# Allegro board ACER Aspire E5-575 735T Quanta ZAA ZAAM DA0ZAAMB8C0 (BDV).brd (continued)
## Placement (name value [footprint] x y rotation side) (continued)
Q22  ioac@ao3413  [SOT23_213-3_3-2]  205.67 190.77 90 bottom
Q23  2n7002dw  [SC70-2_1-65-6P]  178.87 179.22 270 bottom
Q24  ioac@ao3413  [SOT23_213-3_3-2]  48.06 67.58 0 top
Q25  2n7002k  [SOT23_213-3_3-2]  31.17 62.88 270 top
Q26  ap2331sa-7  [SOT23_213-3_3-2]  18.6 58.06 180 top
Q27  *dtc144eu  [UMT_213-3-1_3]  195 50.18 270 bottom
Q28  *ao3404  [SOT23_213-3_3-2]  199.83 51.96 180 bottom
Q29  *pja138k  [SOT23_213-3_3-2]  191.57 50.31 90 bottom
Q30  2n7002k  [SOT23_213-3_3-2]  192.59 31.39 90 bottom
Q31  fdv301n  [SOT23_213-3_3-2]  88.32 130.45 270 bottom
Q32  2n7002dw  [SC70-2_1-65-6P]  148.01 125.62 180 bottom
Q34  ioac@ao6402a  [TSOP6-2_8-95]  222.43 100.48 180 bottom
Q35  *dtc144eu  [UMT_213-3-1_3]  92.89 102.89 0 bottom
Q36  ioac@dmn601k-7  [SOT23_213-3_3-2]  225.35 105.94 0 bottom
Q37  ioac@2n7002dw  [SC70-2_1-65-6P]  225.35 108.86 0 bottom
Q38  *ioac@ao3413  [SOT23_213-3_3-2]  205.29 186.96 270 bottom
Q39  ioac@2n7002k  [SOT23_213-3_3-2]  45.4 80.41 180 top
Q40  pja138k  [SOT23_213-3_3-2]  218.12 67.58 0 bottom
Q41  *2n7002k  [SOT23_213-3_3-2]  25.71 56.79 270 top
Q42  *ao3413  [SOT23_213-3_3-2]  132.52 12.97 90 bottom
Q43  *tdi@2n7002dw  [SC70-2_1-65-6P]  137.72 15.01 180 bottom
Q56  *pj4n3kdw  [SC70-2_1-65-6P]  218.75 71.77 90 bottom
Q59  2n7002k  [SOT23_213-3_3-2]  169.98 109.87 180 bottom
Q75  fpd@ao3413  [SOT23_213-3_3-2]  113.09 32.4 90 top
Q4000  ev@ao3413  [SOT23_213-3_3-2]  170.11 111.02 270 top
Q4001  ev@2n7002k  [SOT23_213-3_3-2]  166.17 111.02 270 top
Q4002  ev@2n7002kw_115ma  [UMT_213-3-1_3]  164.65 116.48 0 top
Q4200  ev@dtc144eu  [UMT_213-3-1_3]  177.89 107.29 270 bottom
Q4201  ev@mmbt3904-7-f  [SOT23_213-3_3-2]  173.55 107.17 270 bottom
Q4202  ev@dtc144eua  [UMT_213-3-1_3]  163.89 135.53 90 bottom
Q4203  ev@metr3904-g  [SOT23_213-3_3-2]  163.63 139.34 90 bottom
Q4300  *ev@me2n7002dkw-g_115ma  [SC70-2_1-65-6P]  191.32 105.94 180 bottom
Q4301  ev@me2n7002dkw-g_115ma  [SC70-2_1-65-6P]  171.38 116.22 0 top
Q4302  ev@me2n7002dkw-g_115ma  [SC70-2_1-65-6P]  185.6 108.86 180 bottom
Q4500  gkb@2n7002d  [SOT23_213-3_3-2]  206.69 159.15 270 bottom
Q4501  gkb@2n7002d  [SOT23_213-3_3-2]  178.11 174.14 0 bottom
Q4509  gka@2n7002d  [SOT23_213-3_3-2]  226.99 117.47 90 top
Q4510  gka@2n7002d  [SOT23_213-3_3-2]  226.12 144.93 270 bottom
Q6059  *2n7002k  [SOT23_213-3_3-2]  159.7 87.78 90 bottom
Q6060  2n7002k  [SOT23_213-3_3-2]  155.89 87.78 90 bottom
Q6062  tyc@aon7401  [POWER-3_3X3_3-65-5P-SMT]  22.28 111.27 180 top
R1  *short_4  [S0402]  128.2 174.14 315 bottom
R2  *short_4  [S0402]  127.56 173.5 315 bottom
R3  tsu@0_4  [R0402]  120.58 178.58 180 bottom
R4  tsu@0_4  [R0402]  120.58 177.57 180 bottom
R5  *tsi@0_4  [R0402]  120.58 178.58 180 top
R6  *tsi@0_4  [R0402]  120.58 177.57 180 top
R7  *tsi@10k_4  [R0402]  134.04 180.61 180 bottom
R8  *tsi@0_4  [R0402]  132.77 180.23 270 bottom
R9  *tsi@10k_4  [R0402]  116.64 175.28 90 top
R10  *tsi@0_4  [R0402]  119.18 176.55 180 top
R11  *short_6  [S0603]  118.8 168.17 270 top
R12  *tsi@10k_4  [R0402]  121.72 174.77 270 top
R13  *tsi@0_4  [R0402]  119.31 173.37 0 top
R14  *short_8  [S0805]  116.39 163.6 270 bottom
R15  *short_8  [S0805]  114.48 162.83 270 bottom
R16  0_6  [R0603]  115.88 171.6 90 top
R19  *0_6  [R0603]  117.15 171.47 90 top
R28  *short_8  [S0805]  114.36 162.83 270 top
R37  *short_4  [S0402]  113.34 157.25 270 bottom
R38  100k_4  [R0402]  113.72 158.52 0 bottom
R52  10k_4  [R0402]  107.88 149.88 180 bottom
R53  *100k_4  [R0402]  111.18 151.53 0 bottom
R58  10k_4  [R0402]  110.42 154.32 180 bottom
R65  100k_4  [R0402]  107.24 155.72 90 bottom
R66  *short_4  [S0402]  109.02 155.72 90 bottom
R67  *short_4  [S0402]  108.13 155.72 90 bottom
R74  1k_4  [R0402]  90.1 131.97 180 bottom
R85  1k_4  [R0402]  147.12 136.29 270 bottom
R89  60.4/f_4  [R0402]  146.11 136.29 90 bottom
R96  100/f_4  [R0402]  129.09 135.94 90 top
R98  100/f_4  [R0402]  128.2 135.94 270 top
R102  *short_4  [S0402]  139.76 134 0 bottom
R103  *0_4  [R0402]  139.76 132.99 0 bottom
R109  100/f_4  [R0402]  131.63 130.7 90 top
R110  *10k_4  [R0402]  148.65 108.22 180 top
R112  *short_6  [S0603]  143.95 128.29 90 top
R113  *0_4  [R0402]  183.19 34.94 0 top
R115  *iv@1k_4  [R0402]  148.65 102.38 180 bottom
R119  *short_4  [S0402]  227.01 127.38 180 bottom
R122  100/f_4  [R0402]  131.63 132.35 90 top
R127  ev@100k_4  [R0402]  146.61 102.38 180 bottom
R130  *10k_4  [R0402]  183.19 35.83 0 top
R131  *0_4  [R0402]  143.06 127.91 270 bottom
R134  54.9/f_4  [R0402]  103.05 130.45 90 bottom
R135  *short_6  [S0603]  134.42 130.19 0 top
R138  100/f_4  [R0402]  101.91 130.58 90 bottom
R145  100/f_4  [R0402]  136.33 120.67 0 top
R148  kbl@10k_4  [R0402]  226.62 122.19 180 bottom
R152  2.2k_4  [R0402]  140.65 118.89 180 top
R153  1.5k/f_4  [R0402]  135.69 121.94 0 top
R154  24.9/f_4  [R0402]  118.59 120.66 180 top
R155  100/f_4  [R0402]  96.7 119.65 180 top
R156  49.9/f_4  [R0402]  106.61 128.42 90 top
R158  49.9/f_4  [R0402]  101.28 119.27 180 top
R160  *10k_4  [R0402]  140.26 116.86 180 top
R161  100/f_4  [R0402]  96.7 118.64 0 top
R162  49.9/f_4  [R0402]  103.69 120.16 180 top
R164  *short_4  [S0402]  151.82 116.61 0 bottom
R165  *2.2k_4  [R0402]  149.15 118.64 180 bottom
R166  2.2k_4  [R0402]  146.61 116.35 90 bottom
R167  2.2k_4  [R0402]  147.63 116.35 90 bottom
R169  *2.2k_4  [R0402]  149.15 117.62 180 bottom
R171  *short_4  [S0402]  144.71 115.84 0 bottom
R172  *gt3@100/f_4  [R0402]  100.51 113.3 0 top
R174  200/f_4  [R0402]  140.65 113.05 0 top
R175  *short_4  [S0402]  144.71 116.86 0 bottom
R176  *gt3@100/f_4  [R0402]  89.46 110.38 90 top
R177  tdi@10k_4  [R0402]  150.55 116.35 270 bottom
R178  113/f_4  [R0402]  140.65 113.94 180 top
R179  *short_6  [S0603]  155.25 112.03 180 top
R180  *short_6  [S0603]  144.84 112.16 0 top
R182  *short_6  [S0603]  144.58 117.62 180 top
R185  *short_6  [S0603]  155.25 109.24 180 top
R186  *short_6  [S0603]  155.25 110.64 180 top
R187  *short_6  [S0603]  144.58 115.97 180 top
R188  *short_6  [S0603]  148.39 113.3 180 top
R190  33_4  [R0402]  172.27 47.77 270 bottom
R192  *short_6  [S0603]  142.93 112.16 270 top
R193  *short_6  [S0603]  145.6 110.26 90 top
R194  *short_4  [S0402]  116.64 108.35 270 top
R195  *1k_4  [R0402]  146.74 109.87 90 top
R196  *10k_4  [R0402]  146.61 100.22 0 bottom
R198  *short_6  [S0603]  155.25 107.97 180 top
R199  *gc6@10k_4  [R0402]  148.65 104.79 0 top
R203  *tyc@0_4  [R0402]  30.28 124.61 90 top
R204  *gc6@10k_4  [R0402]  152.84 104.79 180 top
R205  *150k_4  [R0402]  152.84 97.3 180 top
R206  *tyc@0_4  [R0402]  32.95 124.61 90 top
R207  *1k_4  [R0402]  151.19 108.6 90 top
R208  10k_4  [R0402]  150.3 108.6 270 top
R209  10k_4  [R0402]  229.67 106.57 90 top
R210  *0_6  [R0603]  149.15 116.73 180 top
R211  10k_4  [R0402]  148.9 110.51 180 top
R212  0_6  [R0603]  149.15 115.21 0 top
R213  75/f_4  [R0402]  17.33 75.84 90 top
R214  100k_4  [R0402]  166.17 87.52 270 bottom
R215  10k_4  [R0402]  150.68 103.4 180 top
R216  10k_4  [R0402]  229.67 104.54 270 top
R217  33_4  [R0402]  227.64 104.54 270 top
R218  *10k_4  [R0402]  77.27 121.94 270 bottom
R219  75/f_4  [R0402]  17.33 73.81 90 top
R220  *10k_4  [R0402]  148.65 100.22 180 bottom
R221  *short_8  [S0805]  201.86 189.63 0 bottom
R222  75/f_4  [R0402]  16.57 71.52 90 top
R223  10k_4  [R0402]  150.68 102.38 180 top
R224  *short_4  [S0402]  152.84 102.38 0 top
R227  *10k_4  [R0402]  148.65 102.38 180 top
R228  10k_4  [R0402]  150.68 101.37 180 top
R229  *short_4  [S0402]  152.84 101.37 0 top
R230  ioac@10k_4  [R0402]  204.65 191.23 0 top
R231  *ioac@100k_4  [R0402]  206.56 191.23 0 top
R234  10k_4  [R0402]  150.68 100.22 180 top
R235  *short_4  [S0402]  152.84 100.35 0 top
R237  nac@0_8  [R0805]  201.86 191.54 180 bottom
R239  15_4  [R0402]  181.67 55.26 0 top
R240  *short_6  [S0603]  144.2 110.26 270 top
R241  *10k_4  [R0402]  178.49 178.07 180 top
R242  4.7k_4  [R0402]  180.27 178.07 180 top
R243  *0_4  [R0402]  180.27 179.09 180 top
R244  *0_4  [R0402]  180.27 180.11 0 top
R245  4.7k_4  [R0402]  178.49 180.11 180 top
R246  *short_8  [S0805]  44.51 67.58 180 top
R247  nac@2.2_8  [R0805]  45.52 63.9 180 top
R248  ioac@0_8  [R0805]  45.52 65.68 0 top
R249  1m_4  [R0402]  129.34 102.13 90 top
R250  10k_4  [R0402]  134.42 95.27 270 bottom
R251  75/f_8  [R0805]  24.44 88.28 0 top
R252  *short_6  [S0603]  159.44 90.32 270 top
R253  *0_4  [R0402]  178.49 179.09 0 top
R254  *tyc@0_4  [R0402]  29.9 114.19 270 top
R255  10m_4  [R0402]  139.63 95.02 90 bottom
R256  *100k_4  [R0402]  150.68 104.79 180 top
R257  *10k_4  [R0402]  148.65 103.4 0 top
R258  *tyc@0_4  [R0402]  33.46 114.19 270 top
R259  ioac@10k_4  [R0402]  50.35 70.38 90 top
R260  *ioac@100k_4  [R0402]  49.46 70.38 270 top
R262  75/f_8  [R0805]  24.44 82.32 0 top
R265  *0_4  [R0402]  172.65 90.95 90 bottom
R267  *0_4  [R0402]  173.67 90.88 90 bottom
R268  *0_4  [R0402]  171.63 90.95 90 bottom
R269  75/f_8  [R0805]  24.44 79.27 0 top
R270  *0_4  [R0402]  79.43 77.11 270 top
R271  *0_6  [R0603]  170.11 99.59 270 top
R272  *0_6  [R0603]  167.82 98.95 0 top
R273  *0_4  [R0402]  170.62 90.95 90 bottom
R274  *0_4  [R0402]  169.6 90.95 90 bottom
R275  *49.9k/f_4  [R0402]  156.01 115.77 270 bottom
R276  *0_4  [R0402]  33.58 64.79 90 top
R277  10k/f_4  [R0402]  33.58 62.76 270 top
R278  *0_6  [R0603]  167.82 100.35 180 top
R279  *0_4  [R0402]  168.59 90.95 90 bottom
R280  *49.9k/f_4  [R0402]  155 115.77 270 bottom
R281  *10k/f_4  [R0402]  31.04 60.47 180 top
R282  *0_4  [R0402]  167.57 90.95 90 bottom
R283  *49.9k/f_4  [R0402]  156.9 115.77 270 bottom
R289  *0_6  [R0603]  165.03 100.35 0 top
R290  *49.9k/f_4  [R0402]  154.11 115.77 270 bottom
R291  *0_6  [R0603]  162.87 99.71 270 top
R299  20k/f_4  [R0402]  76.26 47.01 180 top
R300  20k/f_4  [R0402]  76.26 48.03 180 top
R301  45.3k/f_4  [R0402]  77.78 50.18 270 top
R303  *120/f_4  [R0402]  14.53 50.82 270 top
R304  1.5k/f_4  [R0402]  78.92 50.18 90 top
R308  1k_4  [R0402]  73.72 50.95 180 top
R312  *120/f_4  [R0402]  14.53 45.49 270 top
R314  *120/f_4  [R0402]  14.53 47.26 270 top
R315  *120/f_4  [R0402]  14.53 49.04 270 top
R316  2.2k_4  [R0402]  17.96 43.33 270 top
R317  2.2k_4  [R0402]  18.98 43.33 270 top
R318  *short_6  [S0603]  218.5 63.27 0 bottom
R319  2.2k_4  [R0402]  18.47 53.36 270 top
R322  2.2k_4  [R0402]  17.58 53.36 270 top
R326  *0_4  [R0402]  224.59 53.87 270 bottom
R329  *short_4  [S0402]  224.8 60.85 0 bottom
R333  *4.7k_4  [R0402]  220.99 62.76 0 bottom
R334  *4.7k_4  [R0402]  224.92 58.95 180 bottom
R336  *short_4  [S0402]  224.8 59.96 0 bottom
R337  *short_4  [S0402]  224.92 57.04 0 bottom
R338  *short_6  [S0603]  202.37 52.6 90 bottom
R339  *short_8  [S0805]  219.89 45.49 0 bottom
R340  *short_4  [S0402]  21.65 34.56 180 top
R341  *short_4  [S0402]  21.65 33.55 180 top
R342  *short_4  [S0402]  21.65 32.4 180 top
R343  *100k_4  [R0402]  193.86 47.52 0 bottom
R344  *0_4  [R0402]  203.51 49.3 270 bottom
R345  *1m_6  [R0603]  197.16 50.82 90 bottom
R348  *short_4  [S0402]  21.65 31.52 180 top
R349  33_4  [R0402]  180.14 39.77 0 top
R350  *short_4  [S0402]  203.64 47.26 90 bottom
R351  *0_4  [R0402]  224.08 40.41 180 bottom
R352  22k_4  [R0402]  211.77 47.39 90 bottom
R353  *short_4  [S0402]  21.65 30.5 180 top
R354  10k_4  [R0402]  210.75 47.39 270 bottom
R355  *short_4  [S0402]  21.65 29.61 180 top
R356  10k_4  [R0402]  16.95 22.12 270 top
R359  33_4  [R0402]  205.8 47.26 270 bottom
R360  10k_4  [R0402]  16.03 22.12 270 top
R361  *2.2/f_6  [R0603]  190.05 37.87 0 top
R364  100k_4  [R0402]  16.57 28.47 270 top
R365  0_4  [R0402]  207.32 50.18 180 bottom
R366  *0_4  [R0402]  207.32 49.3 180 bottom
R367  *short_6  [S0603]  199.83 49.17 0 bottom
R368  100k_4  [R0402]  191.32 35.2 90 bottom
R369  *10k_4  [R0402]  193.6 44.85 270 bottom
R370  22_4  [R0402]  202.62 47.26 90 bottom
R371  *short_4  [S0402]  201.61 47.26 90 bottom
R372  1k_4  [R0402]  195.64 44.85 90 bottom
R373  *22_4  [R0402]  189.54 36.72 0 bottom
R374  10k_4  [R0402]  161.73 36.09 0 bottom
R375  *0_4  [R0402]  200.08 36.72 180 bottom
R376  39k/f_4  [R0402]  22.66 26.94 0 top
R377  20k/f_4  [R0402]  22.66 27.96 180 top
R378  100k_4  [R0402]  210.88 45.36 90 bottom
R380  100k_4  [R0402]  189.54 34.56 0 bottom
R381  *short_4  [S0402]  18.22 18.94 270 top
R382  ev@10k_4  [R0402]  169.09 29.86 0 bottom
R383  200k_4  [R0402]  211.13 43.83 0 bottom
R384  *short_4  [S0402]  19.23 18.94 270 top
R385  *short_4  [S0402]  20.38 14.62 270 top
R386  *short_4  [S0402]  21.27 14.62 270 top
R387  *short_4  [S0402]  19.23 9.93 90 top
R388  *short_6  [S0603]  211.64 40.53 0 bottom
R389  100k_4  [R0402]  189.54 28.34 180 bottom
R390  *10k/f_4  [R0402]  206.81 33.55 180 bottom
R392  *short_4  [S0402]  18.34 9.93 90 top
R393  *0_4  [R0402]  209.1 45.36 270 bottom
R394  *0_4  [R0402]  196.78 36.85 0 bottom
R395  *29.4k/f_4  [R0402]  206.81 32.53 180 bottom
R397  100k_4  [R0402]  207.32 35.33 180 bottom
R399  *0_4  [R0402]  200.72 32.15 0 bottom
R400  *0_4  [R0402]  212.4 42.56 180 top
R401  *0_4  [R0402]  210.11 35.07 0 top
R402  *short_4  [S0402]  122.2 21.86 270 bottom
R403  *short_4  [S0402]  138.74 16.66 0 bottom
R404  *short_6  [S0603]  76.51 11.07 0 top
R405  *short_4  [S0402]  136.71 13.35 180 bottom
R406  *short_6  [S0603]  76.51 12.34 0 top
R407  2.2k_4  [R0402]  205.67 26.94 90 bottom
R408  *short_4  [S0402]  205.67 24.28 90 bottom
R409  *2.2k_4  [R0402]  138.61 13.35 180 bottom
R410  *2.2k_4  [R0402]  136.84 16.66 0 bottom
R411  *short_4  [S0402]  120.04 19.7 90 bottom
R412  *short_4  [S0402]  121.06 19.7 90 bottom
R414  *short_6  [S0603]  76.51 13.61 0 top
R415  10k_4  [R0402]  120.04 21.99 90 bottom
R416  10k_4  [R0402]  121.06 21.99 90 bottom
R417  *10k_4  [R0402]  201.48 26.18 270 bottom
R418  4.7k_4  [R0402]  201.99 30.12 180 bottom
R419  *short_6  [S0603]  76.51 14.88 0 top
R420  62/f_4  [R0402]  201.48 24.28 270 bottom
R421  4.7k_4  [R0402]  204.27 30.75 270 bottom
R422  62/f_4  [R0402]  202.88 24.28 270 bottom
R423  *10k_4  [R0402]  202.88 26.18 270 bottom
R424  2.2k_4  [R0402]  204.27 26.94 90 bottom
R425  *short_4  [S0402]  204.27 24.28 90 bottom
R426  *1m_4  [R0402]  51.11 18.56 0 top
R427  *1m_4  [R0402]  54.92 18.56 180 top
R428  *1m_4  [R0402]  61.65 18.31 180 top
R429  *1m_4  [R0402]  65.08 18.31 180 top
R430  71.5/f_4  [R0402]  61.65 17.42 180 top
R431  130/f_4  [R0402]  65.08 17.42 180 top
R432  71.5/f_4  [R0402]  53.02 17.55 180 top
R433  130/f_4  [R0402]  54.92 17.55 180 top
R434  *short_6  [S0603]  70.16 14.12 270 top
R435  *100k_4  [R0402]  70.41 12.34 0 top
R436  *1m_4  [R0402]  53.02 18.56 180 top
R437  *short_4  [S0402]  59.62 17.42 0 top
R438  *short_4  [S0402]  51.11 17.55 0 top
R439  *0_4  [R0402]  59.62 16.53 0 top
R440  *0_4  [R0402]  51.11 16.53 0 top
R441  33_4  [R0402]  131.76 178.71 0 bottom
R442  *short_4  [S0402]  128.2 178.84 0 top
R443  *0_4  [R0402]  131.76 180.23 270 bottom
R444  *tsi@10k_4  [R0402]  120.76 168.27 90 bottom
R447  *100k_4  [R0402]  122.74 169.95 0 bottom
R448  *100k_4  [R0402]  122.74 168.93 180 bottom
R449  *100k_4  [R0402]  124.52 168.93 0 bottom
R450  *100k_4  [R0402]  124.52 169.95 180 bottom
R457  33_4  [R0402]  121.85 171.85 0 top
R460  33_4  [R0402]  183.72 48.36 180 bottom
R463  100k_4  [R0402]  169.09 30.75 0 bottom
R465  1k_4  [R0402]  101.4 128.29 270 top
R478  *0_4  [R0402]  94.16 131.97 0 bottom
R485  10k_4  [R0402]  96.07 131.97 0 bottom
R488  *1k_4  [R0402]  92.13 131.97 0 bottom
R512  2.7k/f_4  [R0402]  120.07 124.66 90 top
R513  *1k_4  [R0402]  103.94 130.45 270 bottom
R514  51_4  [R0402]  104.83 130.45 90 bottom
R515  51_4  [R0402]  105.72 130.45 90 bottom
R529  1k_4  [R0402]  104.83 130.45 90 top
R530  100/f_4  [R0402]  104.83 128.42 90 top
R531  499/f_4  [R0402]  100.39 128.29 90 top
R532  *100k_4  [R0402]  98.35 128.29 270 top
R533  *100k_4  [R0402]  99.37 128.29 90 top
R534  51_4  [R0402]  105.72 128.42 90 top
R536  1m_4  [R0402]  113.09 127.78 180 bottom
R537  *51_4  [R0402]  106.61 128.42 90 bottom
R540  10k_4  [R0402]  137.34 128.29 270 bottom
R541  10k_4  [R0402]  138.23 128.29 270 bottom
R542  10k_4  [R0402]  139.25 127.91 270 bottom
R543  10k_4  [R0402]  140.26 127.91 270 bottom
R544  *10k_4  [R0402]  101.4 128.29 90 bottom
R546  *0_4  [R0402]  107.63 132.61 90 bottom
R548  1k_4  [R0402]  96.45 126.64 0 bottom
R550  *short_6  [S0603]  134.8 128.16 0 top
R552  220/f_4  [R0402]  103.05 128.62 270 bottom
R553  *0_4  [R0402]  107.5 130.45 90 bottom
R554  10k_4  [R0402]  100.39 128.29 270 bottom
R555  10k_4  [R0402]  142.04 127.91 270 bottom
R556  *short_4  [S0402]  144.07 127.91 90 bottom
R558  51_4  [R0402]  103.94 128.42 270 bottom
R559  51_4  [R0402]  106.61 130.45 90 bottom
R560  *short_4  [S0402]  180.14 37.87 180 top
R561  10k_4  [R0402]  144.84 126.51 0 bottom
R562  100/f_4  [R0402]  138.36 121.05 90 top
R563  100k_4  [R0402]  145.6 127.91 90 top
R564  100k_4  [R0402]  142.04 121.05 90 top
R565  *gt3@0_6  [R0603]  96.2 129.43 0 bottom
R568  10k_4  [R0402]  145.22 123.46 0 bottom
R569  *10k_4  [R0402]  147.25 121.43 180 bottom
R570  100k_4  [R0402]  145.22 122.45 0 bottom
R571  *short_4  [S0402]  144.71 120.8 90 top
R572  2.2k_4  [R0402]  145.22 124.99 270 bottom
R573  *10k_4  [R0402]  145.22 121.43 180 bottom
R574  *10k_4  [R0402]  145.22 120.54 180 bottom
R575  *10k_4  [R0402]  147.25 120.54 0 bottom
R576  2.2k_4  [R0402]  150.55 125.62 90 bottom
R577  *2.2k_4  [R0402]  140.65 118 180 top
R578  2.2k_4  [R0402]  149.15 123.97 0 bottom
R580  2.2k_4  [R0402]  146.87 127.27 0 bottom
R582  2.2k_4  [R0402]  140.26 115.84 0 top
R585  2.2k_4  [R0402]  148.65 116.35 90 bottom
R586  *1k_4  [R0402]  149.66 116.35 90 bottom
R587  1k_4  [R0402]  143.19 108.35 180 top
R588  15_4  [R0402]  180.78 50.74 90 top
R589  15_4  [R0402]  178.75 50.82 90 top
R590  sp@10k_4  [R0402]  148.65 108.22 0 bottom
R591  10k_4  [R0402]  183.83 50.82 90 top
R592  sp@10k_4  [R0402]  150.68 108.22 0 bottom
R593  10k_4  [R0402]  150.68 109.37 180 bottom
R595  *10k_4  [R0402]  144.58 108.22 0 bottom
R598  sp@10k_4  [R0402]  150.81 107.08 0 bottom
R599  sp@10k_4  [R0402]  148.65 107.08 0 bottom
R600  10k_4  [R0402]  146.61 108.22 180 bottom
R601  2.2k_4  [R0402]  13.39 82.44 180 bottom
R602  *short_4  [S0402]  182.81 50.82 270 top
R605  sp@10k_4  [R0402]  144.58 107.08 0 bottom
R606  *10k_4  [R0402]  146.61 109.37 0 bottom
R607  10k_4  [R0402]  148.65 109.37 180 bottom
R608  sp@10k_4  [R0402]  146.61 107.08 180 bottom
R609  10k_4  [R0402]  77.27 119.91 90 bottom
R610  sp@10k_4  [R0402]  150.68 104.79 0 bottom
R611  *sp@10k_4  [R0402]  148.65 104.79 0 bottom
R612  10k_4  [R0402]  144.58 105.94 0 bottom
R613  *10k_4  [R0402]  146.61 105.94 180 bottom
R614  10k_4  [R0402]  144.58 104.79 0 bottom
R615  *10k_4  [R0402]  146.61 104.79 180 bottom
R616  200/f_4  [R0402]  150.68 102.38 180 bottom
R617  *tyc@4.7k/f_4  [R0402]  27.23 120.29 0 top
R618  *10k_4  [R0402]  150.68 99.21 180 top
R619  *1k_4  [R0402]  150.68 103.4 180 bottom
R620  2.2k_4  [R0402]  13.39 80.41 180 bottom
R621  *10k_4  [R0402]  95.05 103.4 90 bottom
R623  22_4  [R0402]  146.61 101.37 0 bottom
R624  *20k/f_4  [R0402]  146.61 103.4 0 bottom
R625  *1k_4  [R0402]  148.65 103.4 0 bottom
R626  22_4  [R0402]  150.68 100.22 0 bottom
R627  22_4  [R0402]  148.65 101.37 0 bottom
R628  8.2k/f_4  [R0402]  150.81 89.43 0 top
R629  10k_4  [R0402]  146.61 99.21 180 bottom
R630  8.2k/f_4  [R0402]  140.14 91.84 0 bottom
R631  *10k_4  [R0402]  144.58 99.21 180 bottom
R632  *gt3@0_4  [R0402]  91.37 110.38 270 top
R633  *gt3@0_4  [R0402]  100.51 115.08 180 top
R634  *gt3@0_4  [R0402]  100.51 114.19 180 top
R635  49.9/f_4  [R0402]  130.74 102.13 180 top
R636  *gt3@0_4  [R0402]  90.48 110.38 270 top
R639  10k_4  [R0402]  136.33 94 0 bottom
R640  *short_4  [S0402]  136.58 97.3 90 bottom
R642  10k_4  [R0402]  132.52 95.4 90 bottom
R643  *0_4  [R0402]  132.52 93.36 270 bottom
R644  33_4  [R0402]  129.72 97.17 270 bottom
R645  33_4  [R0402]  129.72 93.36 270 bottom
R646  49.9/f_4  [R0402]  132.14 102.76 270 top
R647  *short_4  [S0402]  131.63 90.7 90 bottom
R648  10k_4  [R0402]  132.01 88.79 180 bottom
R649  1k_4  [R0402]  179.76 50.82 90 top
R650  15_4  [R0402]  181.79 50.74 90 top
R651  8.2k/f_4  [R0402]  134.42 97.3 270 bottom
R652  *short_4  [S0402]  136.71 91.84 270 bottom
R653  *short_4  [S0402]  136.84 95.78 180 bottom
R654  15_4  [R0402]  179 53.87 270 top
R655  *short_4  [S0402]  133.28 90.7 270 bottom
R657  *short_8  [S0805]  225.99 103.14 0 bottom
R659  *short_4  [S0402]  136.58 94.89 180 bottom
R660  33_4  [R0402]  130.87 93.36 270 bottom
R661  *short_4  [S0402]  132.52 97.17 90 bottom
R667  33_4  [R0402]  130.87 97.17 270 bottom
R668  *short_4  [S0402]  137.6 97.3 90 bottom
R670  *short_4  [S0402]  153.47 92.98 270 top
R671  nac@0_4  [R0402]  201.22 181.12 0 bottom
R672  nac@0_8  [R0805]  225.48 100.6 90 bottom
R673  ioac@22_8  [R0805]  222.81 103.27 0 bottom
R676  *short_4  [S0402]  134.8 91.84 270 bottom
R677  *short_4  [S0402]  135.82 91.84 270 bottom
R678  80.6/f_4  [R0402]  152.96 91.33 0 top
R679  470_4  [R0402]  154.87 92.73 0 top
R680  ioac@0_4  [R0402]  201.1 180.11 0 bottom
R681  100/f_4  [R0402]  130.61 103.78 180 top
R682  *100k_4  [R0402]  90.61 102.64 270 bottom
R683  *0_6  [R0603]  155.38 89.81 180 top
R684  15_4  [R0402]  180.14 55.77 90 top
R685  120/f_4  [R0402]  152.96 90.44 0 top
R686  ioac@100k  [R0402]  225.1 108.1 0 top
R687  15_4  [R0402]  180.14 53.87 270 top
R688  *short_4  [S0402]  195.64 177.31 180 top
R690  *short_4  [S0402]  195.64 176.42 180 top
R691  15_4  [R0402]  179 55.77 90 top
R692  *ioac@100k  [R0402]  225.1 106.83 180 top
R693  *short_4  [S0402]  195.64 175.53 180 top
R694  *0_4  [R0402]  193.22 174.64 180 top
R695  ioac@100k  [R0402]  227.77 108.48 90 bottom
R696  *short_4  [S0402]  195.64 174.64 180 top
R697  **gt3@10k_4  [R0402]  48.44 83.46 0 top
R698  1k_4  [R0402]  181.67 56.28 180 top
R699  *0_4  [R0402]  191.45 174.64 270 top
R702  ioac@1k_4  [R0402]  42.98 81.05 90 top
R703  *ioac@0_4  [R0402]  225.1 104.79 180 top
R704  ioac@0_4  [R0402]  225.1 105.81 180 top
R705  *gt3@10k_4  [R0402]  48.44 81.55 0 top
R706  **gt3@10k_4  [R0402]  48.44 81.55 180 bottom
R707  *gt3@10k_4  [R0402]  48.44 82.44 180 bottom
R708  **gt3@10k_4  [R0402]  48.44 82.44 0 top
R709  nac@0_4  [R0402]  42.98 79.14 90 top
R710  *ioac@10k_4  [R0402]  206.56 189.76 180 top
R712  **ioac@100k_4  [R0402]  204.65 189.5 180 top
R713  nac@0_4  [R0402]  46.67 77.19 90 top
R714  *10k_4  [R0402]  201.1 182.14 180 bottom
R715  ioac@0_4  [R0402]  45.78 77.19 90 top
R716  **10k_4  [R0402]  202.49 185.57 180 bottom
R717  *10k_4  [R0402]  218.88 72.54 270 top
R718  *short_4  [S0402]  26.09 53.87 270 top
R719  100k_4  [R0402]  219.51 69.11 0 top
R720  20k_4  [R0402]  15.68 58.44 0 top
R721  *short_4  [S0402]  15.68 57.17 0 top
R722  *1m_4  [R0402]  26.98 53.87 270 top
R725  *short_6  [S0603]  169.6 62.76 90 bottom
R729  *tpm@10k_4  [R0402]  166.81 65.35 270 bottom
R730  10k_4  [R0402]  178.75 47.64 270 bottom
R731  4.7k_4  [R0402]  177.6 45.61 270 bottom
R732  4.7k_4  [R0402]  178.49 45.61 270 bottom
R733  2.2k_4  [R0402]  180.9 45.87 270 bottom
R734  2.2k_4  [R0402]  181.92 45.87 270 bottom
R735  *10k_4  [R0402]  173.41 45.61 270 bottom
R736  *10k_4  [R0402]  174.3 45.61 270 bottom
R737  1k_4  [R0402]  129.72 91.46 270 bottom
R738  43_4  [R0402]  182.23 47.77 270 bottom
R739  100k_4  [R0402]  184.33 45.61 270 bottom
R740  ev@10k_4  [R0402]  167.19 29.86 180 bottom
R741  10k_4  [R0402]  173.79 48.66 270 bottom
R742  *short_4  [S0402]  165.66 74.7 90 bottom
R743  *short_4  [S0402]  162.69 69.9 0 bottom
R744  *tpm@4.7k_4  [R0402]  171.76 71.77 90 bottom
R745  *short_6  [S0603]  163.51 65.3 270 bottom
R746  33_4  [R0402]  169.86 44.22 180 bottom
R747  2.2/f_6  [R0603]  186.85 48.08 90 bottom
R749  *short_4  [S0402]  189.54 33.55 0 bottom
R750  *short_4  [S0402]  211.64 38.75 180 bottom
R751  33_4  [R0402]  191.45 27.2 0 bottom
R752  0_6  [R0603]  132.9 15.64 0 bottom
R753  10k_4  [R0402]  216.85 38.63 0 bottom
R754  *0_4  [R0402]  130.1 16.15 180 bottom
R756  *0_4  [R0402]  219.89 70.76 90 top
R757  *0_4  [R0402]  218.88 70.76 90 top
R759  *short_4  [S0402]  144.07 102.64 270 bottom
R760  *short_4  [S0402]  95.05 101.7 90 bottom
R761  100k_4  [R0402]  100.89 130.58 270 bottom
R762  **gt3@0_4  [R0402]  97.64 113.68 0 top
R764  10k_4  [R0402]  148.65 109.37 180 top
R765  *10k_4  [R0402]  150.81 110.51 180 top
R766  sp@10k_4  [R0402]  150.81 105.94 0 bottom
R767  sp@10k_4  [R0402]  148.65 105.94 0 bottom
R774  33_4  [R0402]  168.59 26.18 90 bottom
R775  *0_4  [R0402]  140.52 121.05 90 top
R776  33_4  [R0402]  150.93 17.8 270 bottom
R777  *0_4  [R0402]  141.28 131.97 0 bottom
R778  1k_4  [R0402]  146.61 108.22 0 top
R779  2.2/f_6  [R0603]  190.05 36.34 0 top
R781  20k/f_4  [R0402]  145.6 120.8 90 top
R782  *short_4  [S0402]  189.54 29.86 180 bottom
R783  *0_4  [R0402]  169.73 36.72 90 bottom
R784  *0_4  [R0402]  181.92 38.5 0 top
R785  *0_4  [R0402]  175.32 45.61 270 bottom
R786  100k_4  [R0402]  155.38 90.19 180 bottom
R788  49.9/f_4  [R0402]  105.72 130.45 90 top
R789  0_6  [R0603]  155.38 91.33 180 top
R790  *short_4  [S0402]  195.64 53.74 270 bottom
R791  *short_4  [S0402]  196.14 31.13 0 bottom
R792  *short_4  [S0402]  159.7 31.01 90 bottom
R795  *short_4  [S0402]  107.5 128.42 90 bottom
R796  *short_4  [S0402]  105.72 128.42 90 bottom
R797  *short_4  [S0402]  104.83 128.42 90 bottom
R816  *short_4  [S0402]  18.22 123.59 0 bottom
R817  *short_4  [S0402]  18.22 122.57 0 bottom
R818  *short_4  [S0402]  18.34 115.21 0 top
R819  *short_4  [S0402]  18.34 114.19 0 top
R820  *short_4  [S0402]  18.22 117.62 0 bottom
R821  *short_4  [S0402]  18.22 116.61 0 bottom
R948  *short_8  [S0805]  179.13 93.11 180 bottom
R951  *short_8  [S0805]  179.13 95.78 0 bottom
R956  *short_4  [S0402]  166.43 93.36 90 bottom
R957  *10k_4  [R0402]  165.41 93.36 270 bottom
R958  *short_4  [S0402]  167.06 105.94 270 bottom
R959  *short_4  [S0402]  168.08 105.94 270 bottom
R960  *short_4  [S0402]  163.12 92.73 90 bottom
R961  1m_4  [R0402]  169.6 107.59 0 bottom
R968  *0_4  [R0402]  169.22 105.94 270 bottom
R2854  fpd@10k_4  [R0402]  116.01 32.15 270 top
R2855  *short_4  [S0402]  115.8 17.5 90 bottom
R2868  *fpd_sp@10_4  [R0402]  107.5 23.39 90 bottom
R2870  *short_4  [S0402]  105.72 22.63 90 bottom
R2872  *short_4  [S0402]  108.41 23.41 90 bottom
R4000  ev@10k_4  [R0402]  168.97 113.81 270 top
R4001  ev@10k_4  [R0402]  167.82 108.35 0 top
R4002  ev@100k_4  [R0402]  169.98 113.81 90 top
R4003  *0_8  [R0805]  172.9 110.89 90 top
R4004  *gc6@10k_4  [R0402]  220.54 107.96 270 bottom
R4005  gc6@100k_4  [R0402]  219.53 107.96 90 bottom
R4006  *ev@200/f_4  [R0402]  162.87 143.15 90 bottom
R4007  *ngc6@0_4  [R0402]  217.11 108.72 0 bottom
R4008  ev@10k_4  [R0402]  162.87 131.97 0 bottom
R4009  ev@2.49k/f_4  [R0402]  163.89 143.15 90 bottom
R4010  *short_6  [S0603]  162.87 145.82 180 bottom
R4011  ev@10k_4  [R0402]  165.16 124.35 90 bottom
R4012  gc6@1m_4  [R0402]  229.34 114.02 270 top
R4100  *ev@60.4/f_4  [R0402]  195.51 127.53 0 top
R4102  *ev@60.4/f_4  [R0402]  195.33 133.4 0 top
R4103  *ev@60.4/f_4  [R0402]  184.64 145.92 90 top
R4105  *ev@60.4/f_4  [R0402]  178.75 145.69 90 top
R4114  ev@10k_4  [R0402]  196.91 114.83 90 bottom
R4115  *ev@0_4  [R0402]  194.87 114.83 90 bottom
R4116  *ev@0_4  [R0402]  195.89 114.83 90 bottom
R4117  ev@40.2/f_4  [R0402]  187.89 140.2 180 top
R4118  ev@42.2/f_4  [R0402]  190.68 140.48 90 top
R4119  ev@60.4/f_4  [R0402]  189.67 139.34 270 top
R4200  ev@1.5k/f_4  [R0402]  180.78 106.95 180 bottom
R4201  ev@4.7k_4  [R0402]  175.91 108.44 270 bottom
R4202  *ev@100k/f_4  [R0402]  180.78 105.94 0 bottom
R4203  ev@4.7k_4  [R0402]  172.78 109.87 180 bottom
R4204  ev@4.7k_4  [R0402]  162.87 132.99 0 bottom
R4205  ev@4.7k_4  [R0402]  161.45 132.23 90 bottom
R4206  ev@100k/f_4  [R0402]  164.65 132.99 0 bottom
R4207  ev@4.7k_4  [R0402]  164.27 141.75 180 bottom
R4208  ev@1.8k/f_4  [R0402]  182.17 114.83 270 bottom
R4209  ev@1.8k/f_4  [R0402]  186.24 114.83 270 top
R4210  *ev@10k_4  [R0402]  188.27 112.8 270 top
R4211  ev@10k_4  [R0402]  188.27 114.83 90 top
R4212  ev@10k_4  [R0402]  191.32 114.83 270 bottom
R4300  ev@49.9k/f_4  [R0402]  188.27 112.8 90 bottom
R4301  *ev@45.3k/f_4  [R0402]  195.89 112.8 90 top
R4302  *ev@15k/f_4  [R0402]  190.3 112.8 90 top
R4303  *ev@34.8k/f_4  [R0402]  187.25 112.8 90 top
R4304  *ev@20k/f_4  [R0402]  187.25 112.8 90 bottom
R4305  sp@4.99k/f_4  [R0402]  189.29 112.8 90 top
R4306  sp@4.99k/f_4  [R0402]  196.91 112.8 90 top
R4307  *ev@10k/f_4  [R0402]  190.3 112.8 90 bottom
R4308  *ev@4.99k/f_4  [R0402]  188.27 114.83 90 bottom
R4309  *ev@4.99k/f_4  [R0402]  195.89 114.83 90 top
R4310  *ev@24.9k/f_4  [R0402]  190.3 114.83 90 top
R4311  *ev@4.99k/f_4  [R0402]  187.25 114.83 90 top
R4312  *ev@45.3k/f_4  [R0402]  187.25 114.83 90 bottom
R4313  sp@4.99k/f_4  [R0402]  189.29 114.83 90 top
R4314  sp@4.99k/f_4  [R0402]  196.91 114.83 90 top
R4315  ev@4.99k/f_4  [R0402]  190.3 114.83 90 bottom
R4316  ev@10k_4  [R0402]  184.21 112.8 270 bottom
R4317  ev@10k_4  [R0402]  184.21 114.83 270 bottom
R4318  ev@10k_4  [R0402]  185.22 114.83 90 top
R4319  ev@10k_4  [R0402]  168.59 115.72 180 top
R4320  *ev@10k_4  [R0402]  189.29 110.76 90 bottom
R4321  ev@10k_4  [R0402]  188.27 110.76 90 bottom
R4322  ev@10k_4  [R0402]  183.19 112.8 90 bottom
R4323  *ev@10k_4  [R0402]  185.22 114.83 90 bottom
R4324  ev@10k_4  [R0402]  183.19 114.83 270 bottom
R4325  ev@10k_4  [R0402]  186.24 114.83 90 bottom
R4326  ev@10k_4  [R0402]  189.79 104.29 180 bottom
R4328  *short_4  [S0402]  193.35 104.29 180 bottom
R4329  ev@0_4  [R0402]  191.57 104.29 180 bottom
R4330  *ev@10k_4  [R0402]  162.36 127.4 180 bottom
R4331  *ev@10k_4  [R0402]  162.36 126.38 180 bottom
R4332  *ev@10k_4  [R0402]  162.36 125.37 180 bottom
R4334  ev@10k_4  [R0402]  162.36 128.42 180 bottom
R4335  *short_4  [S0402]  190.05 107.59 0 bottom
R4336  ev@0_4  [R0402]  191.83 107.59 0 bottom
R4337  ev@1.8k/f_4  [R0402]  182.17 112.8 90 bottom
R4338  ev@1.8k/f_4  [R0402]  182.17 114.9 90 top
R4339  ev@1.8k/f_4  [R0402]  181.16 114.83 90 bottom
R4340  ev@1.8k/f_4  [R0402]  181.16 112.8 90 bottom
R4341  ev@2.2k_4  [R0402]  185.48 110.64 0 bottom
R4342  ev@2.2k_4  [R0402]  182.94 108.86 90 bottom
R4343  *ev@10k_4  [R0402]  186.24 112.8 90 bottom
R4344  *ev@10k_4  [R0402]  189.29 112.8 270 bottom
R4345  ev@40.2k/f_4  [R0402]  189.29 114.83 90 bottom
R4346  *ev@0_4  [R0402]  168.59 116.86 180 top
R4510  gkb@549/f_4  [R0402]  203.51 160.67 0 bottom
R4511  gkb@931/f_4  [R0402]  203.51 158.64 180 bottom
R4512  *gkb@549/f_4  [R0402]  203.51 156.48 0 bottom
R4513  *gkb@931/f_4  [R0402]  203.51 157.63 180 bottom
R4514  gkb@549/f_4  [R0402]  203.51 161.69 0 top
R4515  gkb@931/f_4  [R0402]  203.51 163.72 180 top
R4516  *gkb@549/f_4  [R0402]  191.32 171.72 90 top
R4517  *gkb@931/f_4  [R0402]  193.6 171.72 270 top
R4518  gkb@549/f_4  [R0402]  165.28 167.53 180 top
R4519  gkb@931/f_4  [R0402]  165.28 166.39 0 top
R4520  *gkb@549/f_4  [R0402]  171.63 171.6 90 top
R4521  *gkb@931/f_4  [R0402]  174.3 171.6 270 top
R4522  gkb@549/f_4  [R0402]  165.28 161.56 180 bottom
R4523  gkb@931/f_4  [R0402]  165.28 162.83 0 bottom
R4524  *gkb@549/f_4  [R0402]  165.28 167.53 180 bottom
R4525  *gkb@931/f_4  [R0402]  165.28 166.39 0 bottom
R4526  gkb@80.6/f_4  [R0402]  203.13 163.09 90 bottom
R4527  gkb@80.6/f_4  [R0402]  165.66 159.91 270 bottom
R4528  gkb@1.33k/f_4  [R0402]  203.51 159.66 0 bottom
R4529  *gkb@1.33k/f_4  [R0402]  203.51 155.47 0 bottom
R4530  gkb@1.33k/f_4  [R0402]  203.51 162.71 0 top
R4531  *gkb@1.33k/f_4  [R0402]  192.46 171.72 90 top
R4532  gkb@1.33k/f_4  [R0402]  165.28 165.25 180 top
R4533  *gkb@1.33k/f_4  [R0402]  172.78 171.6 90 top
R4534  gkb@1.33k/f_4  [R0402]  165.21 164.1 180 bottom
R4535  *gkb@1.33k/f_4  [R0402]  165.28 165.25 180 bottom
R4538  gkb@10k_4  [R0402]  190.18 171.72 270 top
R4541  gkb@10k_4  [R0402]  176.71 171.6 270 top
R4542  gkb@10k_4  [R0402]  187.89 171.72 270 top
R4543  gkb@10k_4  [R0402]  179.38 171.6 270 top
R4546  gkb@120/f_4  [R0402]  203.51 164.74 0 bottom
R4547  gkb@1k_4  [R0402]  203.51 164.74 0 top
R4548  gkb@1k_4  [R0402]  186.75 171.67 90 top
R4549  gkb@120/f_4  [R0402]  203.51 165.75 0 top
R4550  gkb@1k_4  [R0402]  203.51 161.69 0 bottom
R4551  gkb@1k_4  [R0402]  185.48 163.21 90 top
R4552  gkb@120/f_4  [R0402]  165.28 161.56 180 top
R4553  gkb@1k_4  [R0402]  165.28 158.39 180 top
R4554  gkb@1k_4  [R0402]  183.95 163.21 90 top
R4555  gkb@120/f_4  [R0402]  165.28 164.1 180 top
R4556  gkb@1k_4  [R0402]  165.28 157.37 180 top
R4557  gkb@1k_4  [R0402]  183.44 171.72 90 top
R6308  *2k/f_4  [R0402]  36.51 25.04 270 top
R10842  *short_4  [S0402]  110.67 129.81 270 bottom
R10843  *short_4  [S0402]  109.78 129.81 270 bottom
R10844  *short_4  [S0402]  108.64 131.72 270 bottom
R10845  *short_4  [S0402]  109.53 131.72 270 bottom
R10846  *short_4  [S0402]  143.06 121.69 270 top
R10847  *short_4  [S0402]  99.37 128.29 270 bottom
R10848  *short_4  [S0402]  98.35 128.29 270 bottom
R10871  240/f_4  [R0402]  102.8 51.45 90 top
R10872  *10k_4  [R0402]  147 37.87 180 top
R10873  24.9/f_4  [R0402]  131.17 38.37 0 top
R10875  240/f_4  [R0402]  104.45 46.25 180 top
R10877  10k_4  [R0402]  127.95 47.26 90 top
R10878  2/f_6  [R0603]  129.09 40.15 270 top
R10879  240/f_4  [R0402]  103.82 43.2 270 top
R10880  *10k_4  [R0402]  147 36.85 180 top
R10881  240/f_4  [R0402]  104.83 51.45 90 top
R10882  10k_4  [R0402]  147 38.88 0 top
R10883  1k/f_4  [R0402]  126.42 42.69 0 top
R10884  240/f_4  [R0402]  103.82 51.45 90 top
R10885  240/f_4  [R0402]  116.77 42.82 180 top
R10886  10k_4  [R0402]  147 35.83 0 top
R10887  *0_4  [R0402]  130.74 40.91 0 top
R10888  240/f_4  [R0402]  110.04 41.8 0 top
R10889  *10k_4  [R0402]  128.83 47.26 270 top
R10890  *1k_4  [R0402]  116.77 43.83 0 top
R10891  240/f_4  [R0402]  104.45 47.26 180 top
R10892  240/f_4  [R0402]  110.04 42.82 0 top
R10894  240/f_4  [R0402]  104.45 48.15 180 top
R10895  1k/f_4  [R0402]  127.82 40.53 90 top
R10896  240/f_4  [R0402]  104.83 43.2 270 top
R10921  *1k_4  [R0402]  115.75 56.28 180 top
R10922  240/f_4  [R0402]  104.2 59.07 180 top
R10923  *10k_4  [R0402]  131.37 52.98 270 top
R10924  *10k_4  [R0402]  155.38 57.17 180 top
R10925  240/f_4  [R0402]  110.17 58.57 0 top
R10926  240/f_4  [R0402]  104.32 64.15 180 top
R10927  10k_4  [R0402]  131.37 55.26 270 top
R10928  240/f_4  [R0402]  113.21 56.79 90 top
R10929  240/f_4  [R0402]  104.32 63.14 180 top
R10930  24.9/f_4  [R0402]  114.36 59.96 90 top
R10931  240/f_4  [R0402]  104.2 55.01 180 top
R10932  2/f_6  [R0603]  116.9 58.06 270 top
R10933  240/f_4  [R0402]  110.04 63.77 90 top
R10934  1k/f_4  [R0402]  117.28 64.79 180 top
R10935  *0_4  [R0402]  116.77 60.22 180 top
R10936  240/f_4  [R0402]  104.2 60.22 180 top
R10937  *10k_4  [R0402]  156.65 55.01 90 top
R10938  1k/f_4  [R0402]  116.77 61.23 0 top
R10939  240/f_4  [R0402]  111.05 63.77 90 top
R10940  10k_4  [R0402]  155.38 55.14 180 top
R10941  240/f_4  [R0402]  104.2 56.03 180 top
R10942  240/f_4  [R0402]  104.2 53.99 180 top
R10943  10k_4  [R0402]  156.65 56.66 270 top
R11047  *0_4  [R0402]  78.42 77.11 270 top
R11061  *short_4  [S0402]  165.03 105.94 270 bottom
R11062  *short_4  [S0402]  164.01 105.94 270 bottom
R11064  100k_4  [R0402]  24.95 53.87 270 top
R11065  gka@10k_4  [R0402]  222.94 138.45 180 top
R11066  *gka@931/f_4  [R0402]  223.07 121.18 180 top
R11067  *gka@931/f_4  [R0402]  223.07 121.18 180 bottom
R11068  gka@1k_4  [R0402]  223.07 128.04 0 top
R11069  gka@1k_4  [R0402]  222.94 142.51 0 top
R11070  gka@931/f_4  [R0402]  213.92 113.3 90 bottom
R11071  gka@1k_4  [R0402]  222.94 137.43 0 top
R11072  gka@10k_4  [R0402]  222.94 139.47 180 top
R11073  gka@1k_4  [R0402]  213.54 133.37 0 top
R11074  *gka@549/f_4  [R0402]  223.07 120.16 0 top
R11075  gka@120/f_4  [R0402]  210.88 151.66 90 top
R11076  *gka@1.33k/f_4  [R0402]  222.94 145.56 0 top
R11077  gka@549/f_4  [R0402]  216.21 113.3 270 bottom
R11078  *gka@931/f_4  [R0402]  222.94 146.58 180 top
R11079  gka@931/f_4  [R0402]  207.96 153.56 270 bottom
R11080  gka@10k_4  [R0402]  223.07 128.04 180 bottom
R11081  *gka@549/f_4  [R0402]  223.07 120.16 0 bottom
R11082  *gka@549/f_4  [R0402]  222.94 144.55 0 bottom
R11083  gka@1k_4  [R0402]  222.94 143.53 0 top
R11084  gka@120/f_4  [R0402]  216.97 151.66 90 top
R11085  gka@931/f_4  [R0402]  213.92 113.3 90 top
R11086  gka@10k_4  [R0402]  223.07 129.05 180 top
R11087  *gka@1.33k/f_4  [R0402]  222.94 145.56 0 bottom
R11088  *gka@931/f_4  [R0402]  222.94 146.58 180 bottom
R11089  gka@120/f_4  [R0402]  217.35 113.3 270 top
R11090  gka@1k_4  [R0402]  218.37 113.3 270 top
R11091  gka@1.33k/f_4  [R0402]  215.07 113.3 270 top
R11092  gka@1k_4  [R0402]  223.07 123.21 0 top
R11093  gka@1.33k/f_4  [R0402]  209.99 153.56 90 bottom
R11094  gka@80.6/f_4  [R0402]  212.15 113.56 180 top
R11095  gka@549/f_4  [R0402]  208.97 153.56 90 bottom
R11096  gka@1k_4  [R0402]  213.54 131.97 0 top
R11097  gka@931/f_4  [R0402]  215.96 151.66 270 top
R11098  gka@80.6/f_4  [R0402]  212.4 151.4 180 top
R11099  gka@549/f_4  [R0402]  214.94 151.66 90 top
R11100  gka@1.33k/f_4  [R0402]  213.92 151.66 90 top
R11101  gka@549/f_4  [R0402]  216.21 113.3 270 top
R11102  *gka@1.33k/f_4  [R0402]  223.07 122.19 0 top
R11103  *gka@1.33k/f_4  [R0402]  223.07 122.19 0 bottom
R11104  *gka@549/f_4  [R0402]  222.94 144.55 0 top
R11105  gka@1.33k/f_4  [R0402]  215.07 113.3 270 bottom
R11106  gka@120/f_4  [R0402]  210.5 113.3 270 top
R11107  33_4  [R0402]  171 23.26 0 bottom
R11108  *short_4  [S0402]  214.19 107.83 180 bottom
R11110  *short_4  [S0402]  162.11 92.73 90 bottom
R11111  *short_4  [S0402]  152.84 103.4 0 top
R11112  *short_4  [S0402]  119.56 130.45 90 bottom
R11113  *short_4  [S0402]  118.55 130.45 90 bottom
R11114  10k_4  [R0402]  152.84 98.32 180 top
R11118  0_4  [R0402]  177.73 47.64 270 bottom
R11119  *0_4  [R0402]  176.33 45.61 270 bottom
R11126  *0_6  [R0603]  185.98 51.84 180 top
R11127  0_6  [R0603]  185.98 53.23 180 top
R11129  *short_4  [S0402]  72.07 12.34 180 top
R11131  *short_6  [S0603]  145.22 118.13 180 bottom
R11133  *short_4  [S0402]  155.5 53.49 180 top
R11134  *short_4  [S0402]  154.87 60.98 90 top
R11136  *short_4  [S0402]  39.43 25.55 180 top
R11137  *short_4  [S0402]  42.22 25.55 180 top
R11138  *short_4  [S0402]  44.76 25.55 180 top
R11139  *short_4  [S0402]  26.73 25.04 90 top
R11140  *short_4  [S0402]  152.84 99.33 0 top
R11141  *short_4  [S0402]  32.82 24.66 180 top
R11153  *short_4  [S0402]  168.08 35.07 0 bottom
R11170  *0_4  [R0402]  155.5 52.6 180 top
R11174  *0_4  [R0402]  155.38 62.5 180 top
R11179  *0_4  [R0402]  133.66 79.52 180 bottom
R11180  *0_4  [R0402]  131.63 79.52 0 bottom
R11181  *0_4  [R0402]  79.43 75.08 270 top
R11182  *0_4  [R0402]  78.42 75.08 270 top
R11185  *short_4  [S0402]  82.35 83.97 90 bottom
R11186  *short_4  [S0402]  86.42 83.59 180 bottom
R11187  4.7k_4  [R0402]  26.35 73.04 90 top
R11188  4.7k_4  [R0402]  25.33 73.04 90 top
R11189  *0_4  [R0402]  24.57 63.9 90 top
R11190  *0_4  [R0402]  23.55 63.9 90 top
R11193  *tyc@100k/f_4  [R0402]  32.31 104.41 270 top
R11194  tyc@100k/f_4  [R0402]  29.65 104.41 270 top
R11195  tyc@100k/f_4  [R0402]  19.49 110.51 270 top
R11196  *short_4  [S0402]  18.22 119.65 0 bottom
R11197  tyc@100k/f_4  [R0402]  30.54 104.41 270 top
R11198  tyc@100k/f_4  [R0402]  35.49 112.29 0 top
R11199  *short_4  [S0402]  18.22 118.64 0 bottom
R11200  tyc@10k_4  [R0402]  18.34 112.54 270 top
R11201  tyc@10k_4  [R0402]  28.76 104.41 90 top
R11202  *short_4  [S0402]  18.22 121.56 0 bottom
R11203  tyc@100k/f_4  [R0402]  31.43 104.41 270 top
R11204  tyc@100k/f_4  [R0402]  31.55 111.78 180 top
R11205  tyc@100k/f_4  [R0402]  35.49 111.14 0 top
R11206  tyc@100k/f_4  [R0402]  34.09 104.41 270 top
R11207  *short_4  [S0402]  18.22 120.54 0 bottom
R11208  tyc@100k/f_4  [R0402]  33.2 104.41 270 top
R11209  *tyc@4.7k/f_4  [R0402]  27.23 119.4 0 top
R11210  *tyc@4.99k/f_4  [R0402]  31.68 114.19 90 top
R11211  *tyc@0_4  [R0402]  32.57 114.19 270 top
R11212  *tyc@0_4  [R0402]  32.06 124.61 90 top
R11213  *tyc@0_4  [R0402]  30.79 114.19 270 top
R11214  *tyc@0_4  [R0402]  31.17 124.61 90 top
R11251  20k/f_4  [R0402]  28 101.37 0 top
R11253  *short_4  [S0402]  31.17 25.93 90 top
R11254  *short_4  [S0402]  29.01 25.55 0 top
R11255  *short_4  [S0402]  32.82 26.44 180 top
R11256  *short_4  [S0402]  27.62 25.04 90 top
R11257  *short_6  [S0603]  30.66 72.79 90 top
R11258  *short_4  [S0402]  39.17 64.79 90 top
R11259  *short_4  [S0402]  38.16 66.69 90 top
R11260  ioac@0_4  [R0402]  35.74 64.79 270 top
R11261  nac@0_4  [R0402]  34.73 64.79 270 top
R11262  15k_4  [R0402]  36.76 64.79 90 top
R11263  1k_4  [R0402]  36.76 62.76 270 top
R11264  2.49k/f_4  [R0402]  41.97 78.89 90 top
R11265  75/f_8  [R0805]  24.44 85.49 0 top
R11266  *short_8  [S0805]  41.84 65.3 90 top
R11267  *short_4  [S0402]  20 71.65 270 top
R11268  47_4  [R0402]  11.61 77.49 0 top
R11269  *33_4  [R0402]  9.84 77.49 180 top
R11270  *short_4  [S0402]  20.88 71.65 270 top
R11271  47_4  [R0402]  11.61 78.51 0 top
R11272  *33_4  [R0402]  9.84 78.51 180 top
R11273  12.4k/f_4  [R0402]  19.49 53.36 270 top
R11274  *10k_4  [R0402]  16.57 53.36 270 top
R11275  10k_4  [R0402]  21.39 53.36 270 top
R11276  *0_4  [R0402]  20.5 53.36 270 top
R11277  0_4  [R0402]  15.55 53.36 270 top
R11278  tyc@10k_4  [R0402]  37.27 111.14 180 top
R11279  *short_4  [S0402]  37.27 112.29 180 top
R11280  *short_4  [S0402]  28 102.38 0 top
R11281  *short_4  [S0402]  34.09 102.64 270 top
R11282  *0_4  [R0402]  214.31 89.3 180 bottom
R11283  *short_4  [S0402]  183.95 37.99 0 top
R11284  10k_4  [R0402]  170.74 106.32 180 bottom
R11285  4.7k_4  [R0402]  24.36 73.04 270 top
R11286  *4.7k_4  [R0402]  23.4 73.04 270 top
R11287  fpd_sp@0_4  [R0402]  113.59 34.82 180 top
R11289  *fpd_sp@0_4  [R0402]  106.61 23.39 90 bottom
R11290  *fpd_sp@0_4  [R0402]  109.68 26.84 270 bottom
R11291  *fpd_sp@0_4  [R0402]  110.95 26.84 270 bottom
R11292  fpd_sp@0_4  [R0402]  110.42 18.31 270 bottom
R11293  fpd_sp@0_4  [R0402]  109.53 18.31 270 bottom
R11294  fpd_sp@0_4  [R0402]  108.64 18.31 270 bottom
R11295  fpd_sp@0_4  [R0402]  107.75 18.31 270 bottom
R11296  *fpd_sp@0_4  [R0402]  111.56 31.01 180 top
R11297  *fpd_sp@0_4  [R0402]  110.93 34.44 270 top
R11298  fpd_sp@0_4  [R0402]  109.68 27.6 90 bottom
R11299  fpd_sp@0_4  [R0402]  110.95 27.6 90 bottom
R11300  fpd_sp@0_4  [R0402]  109.68 22.02 90 bottom
R11301  fpd_sp@0_4  [R0402]  110.95 22.02 90 bottom
R11302  *fpd_sp@0_4  [R0402]  109.68 22.78 270 bottom
R11303  *fpd_sp@0_4  [R0402]  110.95 22.78 270 bottom
RP1  *10k_10p8r  [10P8R]  198.3 28.09 270 bottom
RP2  *tyc@dlp11sn900hl2l  [CHOKE-DLP11SN900HL2L-4P-1]  18.22 119.15 180 bottom
RP3  *tyc@dlp11sn900hl2l  [CHOKE-DLP11SN900HL2L-4P-1]  18.22 123.08 0 bottom
RP4  *tyc@dlp11sn900hl2l  [CHOKE-DLP11SN900HL2L-4P-1]  18.22 117.11 180 bottom
RP5  *tyc@dlp11sn900hl2l  [CHOKE-DLP11SN900HL2L-4P-1]  18.22 121.05 180 bottom
SW1  bi_sw  [SW-TME-532-V-6P]  231 121.9 90 bottom
SW2  *power_sw  [SW-TME-532-V-6P]  218.62 32.15 270 bottom
SW4  lid switch  [SW-DS-A40E-4P]  216 92.4 180 bottom
TP12  *  [TP2650]  121.58 118.95 0 top
TP14  *  [TP2650]  128.91 108.64 0 top
TP17  *  [TP2650]  127.44 106.45 0 top
TP19  *  [TP2675]  147.63 110.38 270 top
TP20  *  [TP2650]  123.63 107.84 0 top
TP22  *  [TP2650]  150.81 98.32 0 top
TP23  *  [TP2675]  130.49 101.24 0 top
TP29  *  [TP2675]  135.44 100.73 0 top
TP30  *  [TP2675]  132.52 101.11 0 top
TP31  *  [TP2675]  138.84 97.07 180 bottom
TP34  *  [TP2650]  200.34 45.74 0 bottom
TP44  *  [TP2650]  46.54 71.14 0 top
TP62  *  [TP2650]  107.37 125.11 0 top
TP63  *  [TP2675]  141.15 127.78 180 bottom
TP64  *  [TP2650]  108.51 126.13 0 top
TP65  *  [TP2650]  105.09 121.56 0 top
TP74  *  [TP2675]  149.41 89.43 0 top
TP75  *  [TP2650]  10.09 72.41 0 top
TP76  *  [TP2675]  203.13 171.34 0 top
TP77  *  [TP2650]  185.1 46.68 90 bottom
TP84  *  [TP2675]  133.91 102.51 0 top
TP88  *  [TP2675]  108.9 105.81 0 top
TP89  *  [TP2650]  108.72 128.7 180 bottom
TP90  *  [TP2650]  109.3 127.55 180 bottom
TP91  *  [TP2650]  108.36 129.94 180 bottom
TP92  *  [TP2650]  106.48 122.45 0 top
TP93  *  [TP2650]  116.01 119.15 0 top
TP94  *  [TP2650]  116.8 120.7 0 top
TP95  *  [TP2675]  130.49 108.99 0 top
TP108  *  [TP2675]  172.75 94.18 180 bottom
TP109  *  [TP2675]  159.82 91.08 180 bottom
TP143  *  [TP2675]  17.84 118.38 0 top
TP144  *  [TP2675]  17.84 116.48 0 top
TP150  *  [TP2675]  159.7 92.98 180 bottom
TP153  *  [TP2650]  124.69 46.96 0 top
TP154  *  [TP2650]  124.01 40.79 0 top
TP157  *  [TP2650]  123.37 69.49 0 top
TP158  *  [TP2650]  126.04 47.39 0 top
TP4000  *  [TP2650]  183.95 124.1 0 top
TP4104  *  [TP2650]  189.92 128.67 0 top
TP4105  *  [TP2650]  189.79 134.26 0 top
TP4106  *  [TP2650]  184.71 140.86 0 top
TP4107  *  [TP2650]  177.35 140.1 0 top
TP4300  *  [TP2650]  162.92 124.51 180 bottom
TP4301  *  [TP2650]  163.76 127.53 180 bottom
TP4302  *  [TP2650]  187.25 118.89 0 top
TP4303  *  [TP2650]  163.76 126.26 180 bottom
TP4304  *  [TP2650]  186.49 120.67 0 top
TP4305  *  [TP2650]  165.16 128.29 180 bottom
TP4306  *  [TP2650]  185.22 120.67 0 top
TP4307  *  [TP2650]  163.76 128.8 180 bottom
TP4308  *  [TP2650]  184.71 122.45 0 top
TP4309  *  [TP2650]  185.96 119.5 0 top
TP4333  *  [TP2650]  45.27 71.14 0 top
TP4334  *  [TP2650]  45.27 69.87 0 top
TP4335  *  [TP2650]  46.54 69.87 0 top
TP4336  *  [TP2650]  42.22 70.38 0 top
TP4344  *  [TP2675]  96.32 99.31 180 bottom
TP4354  *  [TP2675]  155.83 114.04 180 bottom
TP4355  *  [TP2675]  153.85 114.19 180 bottom
TP4356  *  [TP2675]  157.38 112.77 180 bottom
TP4357  *  [TP2675]  150.81 114.19 180 bottom
TP4358  *  [TP2675]  168.08 64.03 90 bottom
TP4359  *  [TP2675]  168.08 65.93 90 bottom
TP4360  *  [TP2675]  171.94 67.89 90 bottom
TP4361  *  [TP2675]  172.68 69.67 90 bottom
TP4362  *  [TP2650]  196.63 58.64 180 bottom
TP4363  *  [TP2650]  195.81 57.65 180 bottom
TP4366  *  [TP2650]  150.73 187.83 0 top
TP4367  *  [TP2675]  143.19 97.25 180 bottom
TP4368  *  [TP2675]  154.11 96.16 0 top
TP4369  *  [TP2675]  141.13 97.25 180 bottom
TP4372  *  [TP2675]  147.12 119.4 180 bottom
TP4373  *  [TP2675]  137.22 122.07 0 top
TP4376  *  [TP2650]  22.54 72.41 0 top
TP4377  *  [TP2650]  150.42 106.45 0 top
TP4378  *  [TP2650]  148.9 106.45 0 top
TP4379  *  [TP2650]  132.47 125.75 0 top
TP4380  *  [TP2650]  132.39 127.02 0 top
TP4381  *  [TP2650]  131.35 129.43 180 bottom
TP4382  *  [TP2650]  132.21 131.67 180 bottom
TP4383  *  [TP2650]  146.61 125.11 0 top
TP4384  *  [TP2650]  128.83 133.12 180 bottom
TP4385  *  [TP2650]  145.6 123.59 0 top
TP4386  *  [TP2650]  130.1 133.12 180 bottom
TP4387  *  [TP2650]  118.42 123.21 0 top
TP4389  *  [TP2650]  119.06 124.35 0 top
TP4390  *  [TP2650]  143.95 123.72 0 top
TP4392  *  [TP2650]  109.15 127.27 0 top
TP4393  *  [TP2650]  109.78 128.42 0 top
TP4394  *  [TP2650]  110.09 128.57 180 bottom
TP4395  *  [TP2650]  110.85 127.55 180 bottom
TP4396  *  [TP2650]  113.24 23.79 0 bottom
TP4397  *  [TP2650]  111.92 23.39 0 bottom
U1  ap2821ktr-g1  [SOT23-2_8-95-6P]  110.42 159.4 0 bottom
U6  74aup1g07gw  [SOT353-1-2_125-65-5P]  146.23 134 180 bottom
U8  *tc7sh08fu  [SSOP5-P-A-TOSHIBA-B]  180.14 35.96 0 top
U9  tyc@ptn36242lbs  [TQFN32-3X6-4-41P-0_8H]  31.68 119.4 90 top
U12  apl5606aki  [SOIC8-6-1_27]  78.42 125.5 270 bottom
U13  rl6420_32pin  [QFN32-4X4-4-33P-0_9H]  23.68 68.35 90 top
U14  tc7sh08fu  [SSOP5-P-A-TOSHIBA-B]  163.76 87.78 90 bottom
U15  rtl8411b-cg  [QFN48-6X6-4-49P-ALC280]  37.9 72.66 180 top
U16  *kbl17@kmm40301026-18ds  [MIC-KMM40301026-11DN-8P]  133 84.4 90 top
U17  kmm40301026-18ds  [MIC-KMM40301026-11DN-8P]  83 84.4 90 top
U18  ptn3366bs  [QFN32-5X5-5-37P-0_85H]  18.98 48.28 180 top
U19  gs@lis3dhtr  [LGA16-3X3-5]  220.02 57.04 0 bottom
U20  g524b2t11u  [SOT23-5]  22.92 36.85 180 top
U21  usb30_esd_az1065-06f.r7g  [ESD10-4_1X2-8-11P]  18.09 32.4 270 top
U22  tps2544rter  [QFN16-3X3-5-22P-TPS2544RTER]  18.47 25.55 180 top
U23  alc255  [QFN48-6X6-4-49P-ALC280]  204.78 42.18 0 bottom
U24  usb30_esd_az1065-06f.r7g  [ESD10-4_1X2-8-11P]  18.09 14.24 270 top
U25  *g923-330t1uf  [SOT23-5]  210.11 32.02 0 bottom
U28  tyc@tps25810rvcr(qfn)  [QFN20-4X3-5-27P]  32.06 108.6 90 top
U33  *74aup1g07gw  [SOT353-1-2_125-65-5P]  95.05 133.75 0 bottom
U35  sp@skl_ult/bga  [BGA1356-INTEL-SKYLAKE-U]  120.5 112.4 270 bottom
U36  *rclamp0524p  [SLP10-2_5X1-5-10P]  10.34 81.05 90 top
U37  *m74vhc1gt125df2g  [SSOP5-P-A-TOSHIBA-B]  10.47 87.65 90 top
U38  *rclamp0524p  [SLP10-2_5X1-5-10P]  10.6 74.7 90 top
U40  *m74vhc1gt125df2g  [SSOP5-P-A-TOSHIBA-B]  13.39 87.65 90 top
U41  rom@w25q64fv  -- 8mb  [SOIC8-8-1_27]  180.65 54.38 180 bottom
U42  transformer  [TRF-N1010G-25P]  28.5 82.9 270 bottom
U43  *74aup1g07gw  [SOT353-1-2_125-65-5P]  201.86 183.92 0 bottom
U44  tpm@npct620/650_qfn32  [QFN32-5X5-5-33P-0_85H]  167.44 70.12 180 bottom
U45  it8987/cx  [LQFP128-16X16-4-1_6H]  179.38 35.2 270 bottom
U47  tc7sh08fu  [SSOP5-P-A-TOSHIBA-B]  142.42 133.88 180 bottom
U48  *tc7sh08fu  [SSOP5-P-A-TOSHIBA-B]  193.1 53.61 0 bottom
U49  *tc7sh08fu  [SSOP5-P-A-TOSHIBA-B]  196.78 33.17 180 bottom
U50  *tc7sh08fu  [SSOP5-P-A-TOSHIBA-B]  157.79 31.64 270 bottom
U1006  *fpd_sp@pi3usb102  [TQFN10-1_6X1_3-4-SMT]  110.32 24.81 0 bottom
U3002  sp@n16p-gt  [BGA908-NVIDIA-N13P-GS-A1]  182.23 132.44 180 bottom
U4001  gc6@74ahc1g09gw  [SSOP5-P-A-TOSHIBA-B]  211.27 107.2 180 bottom
U4002  gc6@tc7sh08fu(f)  [SSOP5-P-A-TOSHIBA-B]  217.11 106.69 180 bottom
U4509  tyc@az1043-08f  [ESD-3_8X1-9P]  14.66 120.03 90 bottom
U4511  g524b2t11u  [SOT23-5]  212.53 28.59 180 bottom
U4512  *kbl15@kmm40301026-18ds  [MIC-KMM40301026-11DN-8P]  170.5 84.4 90 top
U4513  tyc@az1045-08f  [ESD-3_8X1-9P]  14.41 115.84 90 top
VRAM3000  gkb@gddr5  [BGA170-HYNIX-H5GQ1H24MJR]  194.53 161.42 90 bottom
VRAM3001  gkb@gddr5  [BGA170-HYNIX-H5GQ1H24MJR]  174.49 161.39 90 top
VRAM3002  gka@gddr5  [BGA170-HYNIX-H5GQ1H24MJR]  213 142.56 0 top
VRAM3003  gka@gddr5  [BGA170-HYNIX-H5GQ1H24MJR]  212.98 122.44 0 bottom
